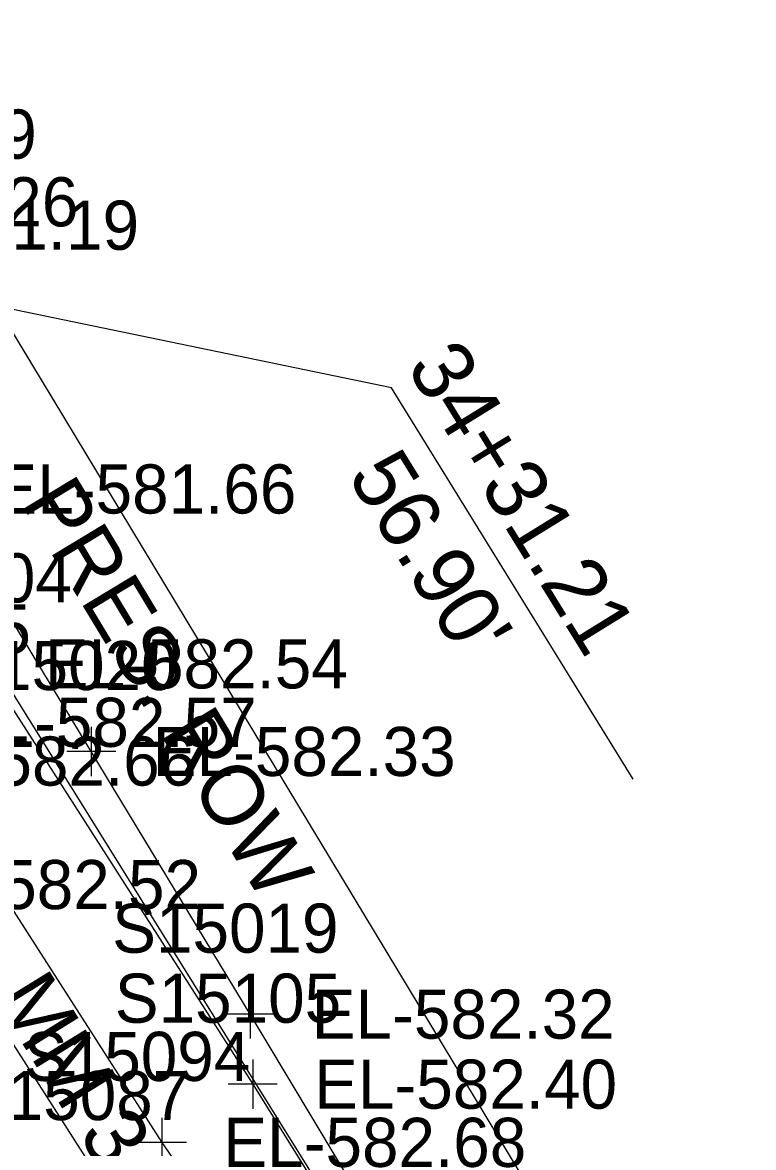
# Model space of a CAD drawing. Extents: x 1729869 to 1735532, y 648588 to 653771.
# Drawn here: x 1731762.7 to 1731822.3, y 651324.1 to 651415.7 of the extents above; entities that cross this region are included whole.
import ezdxf

# ---------------------------------------------------------------- set-up
doc = ezdxf.new("R2010")
doc.units = 0
for name, color, linetype in [('SURVEY - DRAINAGE - Area Shapes', 7, 'Continuous'), ('SURVEY - DTM - Breaklines', 7, 'Continuous'), ('SURVEY - DTM - Breaklines - Points - Elevations', 7, 'Continuous'), ('SURVEY - DTM - Breaklines - Points - Locators', 7, 'Continuous'), ('SURVEY - DTM - Breaklines - Points - Numbers', 7, 'Continuous'), ('SURVEY - NON-TRANSPORTATION - Features', 7, 'Continuous'), ('SURVEY - PROPERTY - ROW Lines', 7, 'Continuous'), ('SURVEY - PROPERTY - ROW Lines - Points - Numbers', 7, 'Continuous'), ('SURVEY - PROPERTY - ROW Lines Text', 7, 'Continuous'), ('SURVEY - PROPERTY - Station and Offset Flags', 7, 'Continuous'), ('SURVEY - TRAFFIC CONTROL - Signs and Devices with Text', 7, 'Continuous'), ('SURVEY - TRANSPORTATION - Features - Points - Elevations', 7, 'Continuous')]:
    doc.layers.add(name, color=color, linetype=linetype)

msp = doc.modelspace()

# ---------------------------------------------------------------- linework, layer by layer
at = {"layer": 'SURVEY - DRAINAGE - Area Shapes'}
msp.add_lwpolyline([(1731977.006, 651015.712), (1731920.484, 650979.525), (1731672.57, 651339.389), (1731746.653, 651385.638)], close=True, dxfattribs=at)
at = {"layer": 'SURVEY - DTM - Breaklines'}
for points in [[(1731329.074, 651966.061), (1731359.729, 651926.546), (1731391.78, 651888.069), (1731423.005, 651848.978), (1731455.159, 651810.576), (1731479.951, 651777.549), (1731506.268, 651734.811), (1731535.375, 651694.144), (1731562.198, 651652.748), (1731588.043, 651609.921), (1731613.605, 651566.913), (1731639.146, 651523.891), (1731667.1, 651482.416), (1731693.639, 651440.035), (1731719.242, 651397.052), (1731747.215, 651355.589), (1731769.127, 651321.344), (1731788.96, 651288.223), (1731795.994, 651292.731)], [(1731584.065, 651656.623), (1731605.003, 651620.792), (1731631.498, 651578.381), (1731656.714, 651535.152), (1731682.444, 651492.251), (1731708.149, 651449.336), (1731734.221, 651406.653), (1731759.562, 651363.503), (1731781.502, 651329.275), (1731801.881, 651296.504), (1731795.994, 651292.731)], [(1731688.347, 651462.061), (1731699.684, 651443.908), (1731725.78, 651401.244), (1731752.138, 651358.745), (1731774.103, 651324.533), (1731795.994, 651292.731), (1731797.002, 651291.324)]]:
    msp.add_lwpolyline(points, dxfattribs=at)
at = {"layer": 'SURVEY - DTM - Breaklines - Points - Locators'}
for p, q in [((1731768.35, 651358.37), (1731768.35, 651354.37)), ((1731770.35, 651356.37), (1731766.35, 651356.37)), ((1731781.305, 651336.978), (1731781.305, 651332.978)), ((1731783.305, 651334.978), (1731779.305, 651334.978)), ((1731781.502, 651331.275), (1731781.502, 651327.275)), ((1731783.502, 651329.275), (1731779.502, 651329.275)), ((1731774.103, 651326.533), (1731774.103, 651322.533)), ((1731776.103, 651324.533), (1731772.103, 651324.533))]:
    msp.add_line(p, q, dxfattribs=at)
at = {"layer": 'SURVEY - NON-TRANSPORTATION - Features'}
msp.add_lwpolyline([(1731794.161, 651313.522), (1731781.305, 651334.978), (1731768.35, 651356.37), (1731755.374, 651377.749), (1731742.559, 651399.232), (1731729.695, 651420.682), (1731716.817, 651442.124), (1731703.914, 651463.55), (1731691.023, 651484.984), (1731678.113, 651506.405), (1731665.144, 651527.788), (1731652.209, 651549.195), (1731639.346, 651570.646), (1731622.506, 651598.643), (1731609.559, 651620.041), (1731596.626, 651641.447), (1731583.632, 651662.815), (1731569.228, 651686.906), (1731556.232, 651708.397), (1731542.125, 651732.02), (1731531.425, 651758.134)], dxfattribs=at)
at = {"layer": 'SURVEY - PROPERTY - ROW Lines'}
msp.add_line((1731760.631, 651392.64), (1731907.344, 651149.681), dxfattribs=at)
at = {"layer": 'SURVEY - PROPERTY - Station and Offset Flags'}
msp.add_line((1731812.502, 651354.105), (1731792.814, 651385.983), dxfattribs=at)
msp.add_lwpolyline([(1731792.814, 651385.983), (1731760.631, 651392.64)], dxfattribs=at)

# ---------------------------------------------------------------- texts
at = {"layer": 'SURVEY - DTM - Breaklines - Points - Elevations'}
for s, p in [('EL-581.19', (1731739.221, 651404.653)), ('EL-581.19', (1731747.559, 651397.232)), ('EL-581.66', (1731760.374, 651375.749)), ('EL-582.54', (1731764.562, 651361.503)), ('EL-582.57', (1731757.138, 651356.745)), ('EL-582.33', (1731773.35, 651354.37)), ('EL-582.66', (1731752.215, 651353.589)), ('EL-582.32', (1731786.305, 651332.978)), ('EL-582.40', (1731786.502, 651327.275)), ('EL-582.68', (1731779.103, 651322.533))]:
    msp.add_text(s, height=4, dxfattribs=at).set_placement(p)
at = {"layer": 'SURVEY - DTM - Breaklines - Points - Numbers'}
for s, p in [('S15104', (1731748.322, 651368.503)), ('S15020', (1731756.937, 651361.37)), ('S15019', (1731770.05, 651339.978)), ('S15105', (1731770.262, 651334.275)), ('S15094', (1731762.863, 651329.533)), ('S15087', (1731757.887, 651326.344))]:
    msp.add_text(s, height=4, dxfattribs=at).set_placement(p)
at = {"layer": 'SURVEY - PROPERTY - ROW Lines - Points - Numbers'}
msp.add_text('SP026', height=4, dxfattribs=at).set_placement((1731751.233, 651399.14))
at = {"layer": 'SURVEY - PROPERTY - ROW Lines Text'}
msp.add_text('PRES. ROW', height=4.998, rotation=301.12615, dxfattribs=at).set_placement((1731762.573, 651376.633))
at = {"layer": 'SURVEY - PROPERTY - Station and Offset Flags'}
for s, p in [('34+31.21', (1731793.955, 651387.704)), ("56.90'", (1731789.157, 651378.82))]:
    msp.add_text(s, height=5, rotation=301.70063, dxfattribs=at).set_placement(p)
at = {"layer": 'SURVEY - TRAFFIC CONTROL - Signs and Devices with Text'}
msp.add_text('MM 3', height=5, rotation=301.66548, dxfattribs=at).set_placement((1731760.413, 651336.309))
at = {"layer": 'SURVEY - TRANSPORTATION - Features - Points - Elevations'}
for s, p in [('EL-582.65', (1731738.738, 651364.345)), ('EL-582.52', (1731752.606, 651343.527))]:
    msp.add_text(s, height=4, dxfattribs=at).set_placement(p)

doc.saveas('drawing.dxf')
